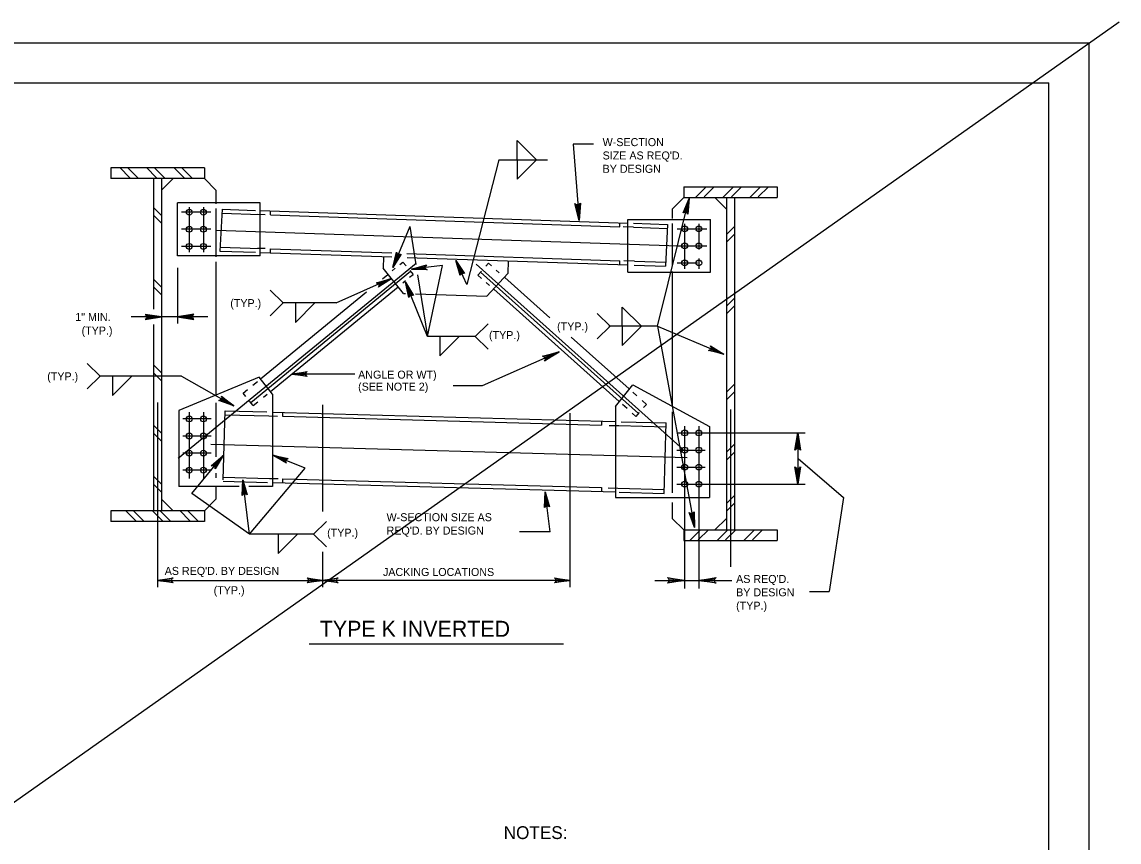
# Model space of a CAD drawing. Extents: x 634656 to 641360, y 298715 to 301183.
# Drawn here: x 635948.6 to 636359.8, y 300207.5 to 300514.8 of the extents above; entities that cross this region are included whole.
import ezdxf

# ---------------------------------------------------------------- set-up
doc = ezdxf.new("R2010")
doc.units = 0
for name, color, linetype in [('1', 7, 'Continuous'), ('2', 7, 'Continuous'), ('PLT-BNDY', 7, 'Continuous')]:
    doc.layers.add(name, color=color, linetype=linetype)

msp = doc.modelspace()

# ---------------------------------------------------------------- linework, layer by layer
at = {"layer": '1'}
for p, q in [((635497.46, 299906.13), (636359.79, 300514.83)), ((636155.15, 300469.04), (636157.39, 300440.45)), ((636127.37, 300463.21), (636115.39, 300416.47)), ((636016.96, 300460.16), (635981.91, 300460.16)), ((635981.91, 300460.16), (635981.91, 300456.16)), ((635989.04, 300456.44), (635985.23, 300460.25)), ((635992.24, 300456.16), (635988.24, 300460.16)), ((635999.07, 300456.44), (635995.26, 300460.25)), ((636002.27, 300456.16), (635998.27, 300460.16)), ((636009.34, 300456.44), (636005.53, 300460.25)), ((636012.54, 300456.16), (636008.55, 300460.16)), ((636016.96, 300460.16), (636016.96, 300456.16)), ((636016.96, 300456.16), (635981.91, 300456.16)), ((635997.94, 300456.16), (635997.94, 300407.18)), ((636000.94, 300456.16), (636000.94, 300331.63)), ((636000.94, 300451.83), (636005.26, 300456.16)), ((636021.29, 300451.83), (636016.96, 300456.16)), ((636021.29, 300451.83), (636021.29, 300446.7)), ((636196.62, 300453.01), (636231.68, 300453.01)), ((636196.62, 300453.01), (636196.62, 300449.01)), ((636201.04, 300449.01), (636205.04, 300453.01)), ((636204.25, 300449.29), (636208.06, 300453.1)), ((636211.31, 300449.01), (636215.31, 300453.01)), ((636214.52, 300449.29), (636218.33, 300453.1)), ((636221.35, 300449.01), (636225.35, 300453.01)), ((636224.55, 300449.29), (636228.36, 300453.1)), ((636231.68, 300453.01), (636231.68, 300449.01)), ((636006.95, 300427.25), (636006.95, 300447.01)), ((636037.89, 300447.01), (636006.95, 300447.01)), ((636011.3, 300445.42), (636011.3, 300428.55)), ((636016.61, 300445.42), (636016.61, 300428.55)), ((636037.89, 300427.25), (636037.89, 300447.01)), ((636186.85, 300400.8), (636198.66, 300448.68)), ((636192.3, 300444.68), (636196.62, 300449.01)), ((636196.62, 300449.01), (636231.68, 300449.01)), ((636212.65, 300444.68), (636208.32, 300449.01)), ((636212.65, 300449.01), (636212.65, 300324.48)), ((636215.65, 300449.01), (636215.65, 300324.48)), ((636000.94, 300442.34), (635997.94, 300445.34)), ((636000.94, 300439.42), (635997.94, 300442.42)), ((636019.43, 300443.52), (636008.34, 300443.52)), ((636021.29, 300444.9), (636021.29, 300426.84)), ((636023.6, 300444.65), (636022.81, 300428.97)), ((636023.55, 300443.15), (636037.89, 300442.67)), ((636023.6, 300444.65), (636036.17, 300444.23)), ((636039.77, 300442.6), (636037.06, 300442.69)), ((636037.89, 300444.17), (636175.7, 300439.49)), ((636041.79, 300442.61), (636041.79, 300444.11)), ((636041.79, 300442.53), (636172.7, 300438.09)), ((636192.3, 300444.68), (636192.3, 300441.14)), ((636093.99, 300438.14), (636087.63, 300422.85)), ((636093.99, 300438.14), (636096.28, 300423.9)), ((636172.7, 300438.09), (636172.7, 300439.54)), ((636177.81, 300437.92), (636173.97, 300438.05)), ((636175.7, 300421.04), (636175.7, 300440.81)), ((636175.7, 300440.81), (636206.63, 300440.81)), ((636177.81, 300437.92), (636190.56, 300437.49)), ((636177.86, 300439.42), (636190.61, 300438.98)), ((636190.61, 300438.98), (636189.82, 300423.3)), ((636192.3, 300439.34), (636192.3, 300423.46)), ((636194.16, 300437.32), (636205.25, 300437.32)), ((636196.98, 300439.22), (636196.98, 300422.35)), ((636202.29, 300439.22), (636202.29, 300429.6)), ((636206.63, 300421.04), (636206.63, 300440.81)), ((636212.65, 300435.19), (636215.65, 300438.2)), ((636019.43, 300437.13), (636008.34, 300437.13)), ((636021.33, 300436.87), (636194.77, 300430.99)), ((636212.65, 300432.27), (636215.65, 300435.27)), ((636019.43, 300430.74), (636008.34, 300430.74)), ((636022.81, 300428.97), (636036.18, 300428.51)), ((636022.86, 300430.47), (636037.89, 300429.96)), ((636039.79, 300429.89), (636036.91, 300429.99)), ((636041.79, 300428.39), (636041.79, 300429.82)), ((636041.79, 300429.82), (636087.18, 300428.28)), ((636194.16, 300430.93), (636205.25, 300430.93)), ((636037.89, 300427.25), (636006.95, 300427.25)), ((636021.29, 300424.93), (636021.29, 300375.04)), ((636037.89, 300428.46), (636087.19, 300426.78)), ((636084.16, 300426.88), (636084.02, 300422.57)), ((636090.24, 300423.94), (636091.38, 300424.88)), ((636091.38, 300424.88), (636092.58, 300423.42)), ((636092.81, 300428.09), (636172.7, 300425.38)), ((636093.02, 300426.58), (636175.7, 300423.78)), ((636115.39, 300416.47), (636111.23, 300425.46)), ((636130.84, 300425.3), (636130.68, 300420.6)), ((636172.7, 300423.83), (636172.7, 300425.38)), ((636178.12, 300425.2), (636174.17, 300425.33)), ((636178.12, 300425.2), (636189.87, 300424.8)), ((636202.29, 300426.22), (636202.29, 300422.35)), ((636006.95, 300422.71), (636006.95, 300401.87)), ((636007.09, 300351.43), (636096.38, 300424.49)), ((636034.34, 300372.21), (636094.24, 300421.4)), ((636091.58, 300413.09), (636084.02, 300422.57)), ((636087.31, 300421.53), (636088.54, 300422.54)), ((636093.98, 300421.72), (636095.19, 300420.24)), ((636106.2, 300423.56), (636094.58, 300422.14)), ((636100.62, 300396.97), (636106.2, 300423.56)), ((636196.47, 300354.59), (636118.84, 300424.04)), ((636120.83, 300421.43), (636119.51, 300419.95)), ((636179.66, 300368.15), (636120.51, 300421.07)), ((636123.51, 300424.42), (636122.48, 300423.27)), ((636124.61, 300423.43), (636123.51, 300424.42)), ((636127.48, 300420.87), (636126.37, 300421.86)), ((636175.7, 300421.04), (636206.63, 300421.04)), ((636178.07, 300423.7), (636189.82, 300423.3)), ((636192.3, 300421.37), (636192.3, 300370.88)), ((636194.16, 300424.53), (636201.8, 300424.53)), ((636000.94, 300415.51), (635997.94, 300418.51)), ((636066.32, 300409.52), (636087.13, 300418.84)), ((636083.74, 300418.6), (636085.69, 300420.2)), ((636091.33, 300417.07), (636092.4, 300417.95)), ((636100.62, 300396.97), (636092.31, 300417.32)), ((636093.9, 300419.18), (636095.19, 300420.24)), ((636096.89, 300420.1), (636100.62, 300396.97)), ((636120.86, 300418.74), (636119.51, 300419.95)), ((636123.87, 300416.05), (636122.58, 300417.21)), ((636122.84, 300412.03), (636130.68, 300420.6)), ((636146.44, 300403.91), (636129.52, 300419.04)), ((636000.94, 300412.59), (635997.94, 300415.59)), ((636038.04, 300381.07), (636077.75, 300413.68)), ((636041.79, 300376.39), (636089.56, 300415.62)), ((636091.58, 300413.09), (636092.31, 300413.07)), ((636096.13, 300412.94), (636122.84, 300412.03)), ((636172.44, 300372.6), (636125.44, 300414.64)), ((636212.65, 300408.36), (636215.65, 300411.36)), ((636212.65, 300405.44), (636215.65, 300408.44)), ((635997.94, 300401.46), (635997.94, 300331.63)), ((636186.85, 300400.8), (636200.62, 300325.4)), ((636186.85, 300400.8), (636211.67, 300390.37)), ((636176.16, 300377.32), (636154.49, 300396.71)), ((636149.94, 300391.23), (636121.12, 300378.46)), ((636000.94, 300383.3), (635997.94, 300386.3)), ((636000.94, 300380.38), (635997.94, 300383.38)), ((636037.45, 300381.76), (636007.35, 300369.25)), ((636008.38, 300382.08), (636027.95, 300370.94)), ((636035.13, 300378.68), (636036.93, 300380.15)), ((636042.54, 300375.38), (636037.45, 300381.76)), ((636031.48, 300375.68), (636033.15, 300377.06)), ((636032.47, 300374.48), (636031.48, 300375.68)), ((636171.04, 300370.72), (636177.57, 300378.9)), ((636179.1, 300374.7), (636177.52, 300376.1)), ((636177.57, 300378.9), (636206.24, 300363.29)), ((636212.65, 300376.15), (636215.65, 300379.15)), ((636212.65, 300373.23), (636215.65, 300376.23)), ((635999.44, 300372.21), (635999.44, 300313.77)), ((636021.29, 300372.07), (636021.29, 300351.86)), ((636035.29, 300371.05), (636033.89, 300372.75)), ((636035.29, 300371.05), (636037.06, 300372.5)), ((636039.16, 300374.22), (636040.47, 300375.3)), ((636042.54, 300375.38), (636042.54, 300340.77)), ((636061.26, 300371.41), (636061.26, 300331.36)), ((636175.41, 300369.94), (636173.65, 300371.52)), ((636182.66, 300371.5), (636181, 300372.99)), ((636182.66, 300371.5), (636181.59, 300370.3)), ((636007.35, 300369.25), (636007.35, 300340.77)), ((636011.3, 300368.62), (636011.3, 300343.72)), ((636016.61, 300368.62), (636016.61, 300343.72)), ((636024.04, 300343.26), (636024.76, 300369.15)), ((636024.72, 300367.66), (636041.15, 300367.2)), ((636024.76, 300369.15), (636040.35, 300368.72)), ((636042.43, 300368.66), (636170.96, 300365.1)), ((636046.3, 300368.62), (636046.3, 300367.06)), ((636153.97, 300368.29), (636153.97, 300302.99)), ((636171.04, 300370.72), (636171.04, 300336.65)), ((636178.66, 300367.03), (636177.32, 300368.24)), ((636179.97, 300368.49), (636178.66, 300367.03)), ((636192.3, 300368.74), (636192.3, 300338.39)), ((636214.15, 300369.66), (636214.15, 300310.65)), ((636000.94, 300360.72), (635997.94, 300363.72)), ((636019.54, 300366.07), (636008.95, 300366.07)), ((636041.15, 300367.2), (636044.39, 300367.11)), ((636046.3, 300367.06), (636165.84, 300363.74)), ((636165.84, 300365.15), (636165.84, 300363.74)), ((636168.71, 300363.66), (636172.29, 300363.56)), ((636172.29, 300363.56), (636190.01, 300363.07)), ((636173.21, 300365.03), (636190.05, 300364.57)), ((636189.32, 300338.19), (636190.05, 300364.57)), ((636196.98, 300363.37), (636196.98, 300302.6)), ((636202.29, 300363.37), (636202.29, 300302.6)), ((636206.24, 300363.29), (636206.24, 300336.65)), ((636000.94, 300357.79), (635997.94, 300360.8)), ((636019.54, 300359.68), (636008.95, 300359.68)), ((636194.04, 300360.82), (636242.12, 300360.82)), ((636239.34, 300360.82), (636239.34, 300341.64)), ((636019.33, 300356.59), (636197.89, 300351.64)), ((636212.65, 300353.57), (636215.65, 300356.57)), ((636019.54, 300353.29), (636008.95, 300353.29)), ((636012.21, 300338.1), (636023.98, 300352.43)), ((636054.72, 300347.65), (636042.68, 300352.52)), ((636194.04, 300354.43), (636204.63, 300354.43)), ((636212.65, 300350.65), (636215.65, 300353.65)), ((636239.52, 300351.23), (636256.55, 300336.59)), ((636019.54, 300346.89), (636008.95, 300346.89)), ((636033.94, 300322.93), (636054.72, 300347.65)), ((636194.04, 300348.04), (636204.63, 300348.04)), ((636000.94, 300341.59), (635997.94, 300344.59)), ((636021.29, 300345.76), (636021.29, 300344.06)), ((636024.03, 300342.78), (636040.68, 300342.32)), ((636024.07, 300344.28), (636041.36, 300343.8)), ((636033.94, 300322.93), (636031.35, 300343.28)), ((636041.36, 300343.8), (636044.58, 300343.71)), ((636046.3, 300343.66), (636165.84, 300340.34)), ((636046.3, 300343.66), (636046.3, 300342.23)), ((636000.94, 300338.67), (635997.94, 300341.67)), ((636030.07, 300340.77), (636007.35, 300340.77)), ((636021.29, 300340.77), (636021.29, 300335.96)), ((636042.54, 300340.77), (636033.62, 300340.77)), ((636042.6, 300342.26), (636171.12, 300338.7)), ((636146.54, 300323.76), (636144.64, 300338.75)), ((636165.84, 300340.34), (636165.84, 300338.76)), ((636168.31, 300340.28), (636171.89, 300340.18)), ((636171.89, 300340.18), (636189.36, 300339.69)), ((636172.48, 300338.66), (636189.32, 300338.19)), ((636194.04, 300341.64), (636242.12, 300341.64)), ((636000.94, 300335.96), (636005.26, 300331.63)), ((636033.94, 300322.93), (636012.21, 300338.1)), ((636016.96, 300331.63), (636021.29, 300335.96)), ((636171.04, 300336.65), (636206.24, 300336.65)), ((636192.3, 300334.76), (636192.3, 300328.81)), ((636212.65, 300334.44), (636215.65, 300337.44)), ((636212.65, 300331.52), (636215.65, 300334.52)), ((636256.55, 300336.59), (636251.14, 300301.37)), ((636016.96, 300331.63), (635981.91, 300331.63)), ((635981.91, 300331.63), (635981.91, 300327.63)), ((635991.22, 300327.91), (635987.41, 300331.72)), ((635994.42, 300327.63), (635990.42, 300331.63)), ((636001.25, 300327.91), (635997.44, 300331.72)), ((636004.45, 300327.63), (636000.46, 300331.63)), ((636011.52, 300327.91), (636007.71, 300331.72)), ((636014.73, 300327.63), (636010.73, 300331.63)), ((636016.96, 300331.63), (636016.96, 300327.63)), ((636016.96, 300327.63), (635981.91, 300327.63)), ((636196.62, 300324.48), (636192.3, 300328.81)), ((636212.65, 300328.81), (636208.32, 300324.48)), ((636196.62, 300324.48), (636231.68, 300324.48)), ((636196.62, 300324.48), (636196.62, 300320.48)), ((636198.86, 300320.48), (636202.86, 300324.48)), ((636202.06, 300320.76), (636205.87, 300324.58)), ((636209.13, 300320.48), (636213.13, 300324.48)), ((636212.33, 300320.76), (636216.14, 300324.58)), ((636219.17, 300320.48), (636223.16, 300324.48)), ((636222.37, 300320.76), (636226.18, 300324.58)), ((636231.68, 300324.48), (636231.68, 300320.48)), ((636196.62, 300320.48), (636231.68, 300320.48)), ((636061.26, 300316.33), (636061.26, 300302.99)), ((635999.44, 300313.77), (635999.44, 300302.99)), ((636153.97, 300313.77), (636153.97, 300302.99)), ((636185.81, 300305.58), (636196.98, 300305.58)), ((636196.98, 300305.58), (636202.29, 300305.58)), ((636202.29, 300305.58), (636214.67, 300305.58)), ((636243.73, 300301.37), (636251.14, 300301.37))]:
    msp.add_line(p, q, dxfattribs=at)
for points in [[(636157.68, 300446.62), (636157.25, 300446.36), (636157.39, 300440.45), (636157.68, 300446.62), (636157.92, 300446.95), (636157.39, 300440.45), (636156.64, 300446.3), (636156.18, 300446.48), (636157.39, 300440.45), (636155.86, 300446.79), (636156.18, 300446.48)], [(636196.66, 300443.47), (636197.1, 300443.58), (636198.66, 300448.68), (636196.66, 300443.47), (636196.36, 300443.26), (636198.66, 300448.68), (636197.64, 300443.45), (636197.98, 300443.16), (636198.66, 300448.68), (636198.16, 300442.81), (636197.98, 300443.16)], [(636090.4, 300427.69), (636089.95, 300427.66), (636087.63, 300422.85), (636090.4, 300427.69), (636090.73, 300427.86), (636087.63, 300422.85), (636089.43, 300427.87), (636089.14, 300428.2), (636087.63, 300422.85), (636089.01, 300428.58), (636089.14, 300428.2)], [(636112.92, 300420.14), (636113.2, 300420.5), (636111.23, 300425.46), (636112.92, 300420.14), (636112.82, 300419.78), (636111.23, 300425.46), (636113.71, 300420.73), (636114.15, 300420.72), (636111.23, 300425.46), (636114.51, 300420.56), (636114.15, 300420.72)], [(636100.16, 300422.12), (636099.9, 300422.49), (636094.58, 300422.14), (636100.16, 300422.12), (636100.47, 300421.92), (636094.58, 300422.14), (636099.83, 300423.05), (636099.98, 300423.46), (636094.58, 300422.14), (636100.24, 300423.76), (636099.98, 300423.46)], [(636081.79, 300416.98), (636082.14, 300416.7), (636087.11, 300418.65), (636081.79, 300416.98), (636081.43, 300417.08), (636087.11, 300418.65), (636082.38, 300416.2), (636082.36, 300415.75), (636087.11, 300418.65), (636082.2, 300415.39), (636082.36, 300415.75)], [(636093.76, 300411.93), (636094.05, 300412.27), (636092.31, 300417.32), (636093.76, 300411.93), (636093.64, 300411.58), (636092.31, 300417.32), (636094.57, 300412.49), (636095.01, 300412.46), (636092.31, 300417.32), (636095.37, 300412.28), (636095.01, 300412.46)], [(635995.14, 300403.57), (635995.35, 300403.99), (636000.94, 300404.3), (635995.14, 300403.57), (635994.84, 300403.32), (636000.94, 300404.3), (635995.36, 300404.58), (635995.15, 300404.99), (636000.94, 300404.3), (635994.84, 300405.27), (635995.15, 300404.99)], [(636012.75, 300405.03), (636012.54, 300404.61), (636006.95, 300404.3), (636012.75, 300405.03), (636013.05, 300405.28), (636006.95, 300404.3), (636012.53, 300404.02), (636012.74, 300403.61), (636006.95, 300404.3), (636013.05, 300403.33), (636012.74, 300403.61)], [(636206.84, 300393.15), (636206.87, 300392.7), (636211.67, 300390.37), (636206.84, 300393.15), (636206.67, 300393.49), (636211.67, 300390.37), (636206.66, 300392.19), (636206.33, 300391.9), (636211.67, 300390.37), (636205.95, 300391.77), (636206.33, 300391.9)], [(636144.02, 300389.45), (636144.41, 300389.14), (636149.94, 300391.23), (636144.02, 300389.45), (636143.62, 300389.57), (636149.94, 300391.23), (636144.66, 300388.58), (636144.64, 300388.09), (636149.94, 300391.23), (636144.46, 300387.68), (636144.64, 300388.09)], [(636055.23, 300382.25), (636055.02, 300382.65), (636049.69, 300382.87), (636055.23, 300382.25), (636055.52, 300382.01), (636049.69, 300382.87), (636055.01, 300383.2), (636055.2, 300383.6), (636049.69, 300382.87), (636055.49, 300383.87), (636055.2, 300383.6)], [(636023.48, 300374.28), (636023.46, 300373.83), (636027.95, 300370.94), (636023.48, 300374.28), (636023.36, 300374.63), (636027.95, 300370.94), (636023.19, 300373.34), (636022.82, 300373.09), (636027.95, 300370.94), (636022.43, 300373.01), (636022.82, 300373.09)], [(636238.57, 300354.69), (636239.01, 300354.92), (636239.34, 300360.82), (636238.57, 300354.69), (636238.3, 300354.38), (636239.34, 300360.82), (636239.63, 300354.92), (636240.07, 300354.71), (636239.34, 300360.82), (636240.36, 300354.38), (636240.07, 300354.71)], [(636019.93, 300348.59), (636020.37, 300348.49), (636023.98, 300352.43), (636019.93, 300348.59), (636019.56, 300348.52), (636023.98, 300352.43), (636020.8, 300348.14), (636020.99, 300347.74), (636023.98, 300352.43), (636021, 300347.34), (636020.99, 300347.74)], [(636047.55, 300349.8), (636047.51, 300350.25), (636042.68, 300352.52), (636047.55, 300349.8), (636047.72, 300349.47), (636042.68, 300352.52), (636047.72, 300350.77), (636048.05, 300351.06), (636042.68, 300352.52), (636048.42, 300351.2), (636048.05, 300351.06)], [(636240.11, 300347.77), (636239.67, 300347.55), (636239.34, 300341.64), (636240.11, 300347.77), (636240.38, 300348.09), (636239.34, 300341.64), (636239.05, 300347.54), (636238.61, 300347.76), (636239.34, 300341.64), (636238.32, 300348.09), (636238.61, 300347.76)], [(636031.36, 300337.7), (636031.73, 300337.95), (636031.35, 300343.28), (636031.36, 300337.7), (636031.15, 300337.39), (636031.35, 300343.28), (636032.28, 300338.03), (636032.7, 300337.88), (636031.35, 300343.28), (636033, 300337.62), (636032.7, 300337.88)], [(636144.64, 300333.17), (636145.02, 300333.43), (636144.64, 300338.75), (636144.64, 300333.17), (636144.44, 300332.86), (636144.64, 300338.75), (636145.57, 300333.5), (636145.99, 300333.36), (636144.64, 300338.75), (636146.29, 300333.1), (636145.99, 300333.36)], [(636200.3, 300330.98), (636199.95, 300330.7), (636200.62, 300325.4), (636200.3, 300330.98), (636200.49, 300331.3), (636200.62, 300325.4), (636199.4, 300330.6), (636198.98, 300330.72), (636200.62, 300325.4), (636198.66, 300330.96), (636198.98, 300330.72)], [(636004.97, 300304.88), (636004.77, 300305.28), (635999.44, 300305.58), (636004.97, 300304.88), (636005.26, 300304.64), (635999.44, 300305.58), (636004.76, 300305.84), (636004.96, 300306.24), (635999.44, 300305.58), (636005.26, 300306.5), (636004.96, 300306.24)], [(636055.72, 300306.27), (636055.93, 300305.87), (636061.26, 300305.58), (636055.72, 300306.27), (636055.44, 300306.52), (636061.26, 300305.58), (636055.93, 300305.31), (636055.74, 300304.92), (636061.26, 300305.58), (636055.44, 300304.65), (636055.74, 300304.92)], [(636066.79, 300304.88), (636066.59, 300305.28), (636061.26, 300305.58), (636066.79, 300304.88), (636067.08, 300304.64), (636061.26, 300305.58), (636066.58, 300305.84), (636066.78, 300306.24), (636061.26, 300305.58), (636067.08, 300306.5), (636066.78, 300306.24)], [(636148.43, 300306.27), (636148.64, 300305.87), (636153.97, 300305.58), (636148.43, 300306.27), (636148.15, 300306.52), (636153.97, 300305.58), (636148.64, 300305.31), (636148.45, 300304.92), (636153.97, 300305.58), (636148.15, 300304.65), (636148.45, 300304.92)], [(636190.85, 300306.35), (636191.08, 300305.9), (636196.98, 300305.58), (636190.85, 300306.35), (636190.53, 300306.62), (636196.98, 300305.58), (636191.08, 300305.29), (636190.87, 300304.85), (636196.98, 300305.58), (636190.53, 300304.55), (636190.87, 300304.85)], [(636208.42, 300304.81), (636208.19, 300305.25), (636202.29, 300305.58), (636208.42, 300304.81), (636208.73, 300304.54), (636202.29, 300305.58), (636208.18, 300305.87), (636208.4, 300306.31), (636202.29, 300305.58), (636208.73, 300306.6), (636208.4, 300306.31)]]:
    msp.add_lwpolyline(points, dxfattribs=at)
for centre in [(636011.3, 300443.52), (636016.61, 300443.52), (636011.3, 300437.13), (636016.61, 300437.13), (636196.98, 300437.32), (636202.29, 300437.32), (636011.3, 300430.74), (636016.61, 300430.74), (636196.98, 300430.93), (636202.29, 300430.93), (636196.98, 300424.53), (636202.29, 300424.53), (636011.3, 300366.07), (636016.61, 300366.07), (636011.3, 300359.68), (636016.61, 300359.68), (636196.98, 300360.82), (636202.29, 300360.82), (636196.98, 300354.43), (636202.29, 300354.43), (636011.3, 300353.29), (636016.61, 300353.29), (636011.3, 300346.89), (636016.61, 300346.89), (636196.98, 300348.04), (636202.29, 300348.04), (636196.98, 300341.64), (636202.29, 300341.64)]:
    msp.add_circle(centre, 1.09, dxfattribs=at)
at = {"layer": '2'}
for p, q in [((635547.42, 300491.99), (636333.42, 300491.99)), ((636333.42, 299927.99), (636333.42, 300491.99)), ((636134.18, 300463.21), (636134.18, 300470.46)), ((636134.18, 300470.46), (636141.43, 300463.21)), ((636162.79, 300469.04), (636155.15, 300469.04)), ((636127.37, 300463.21), (636145.6, 300463.21)), ((636134.18, 300463.21), (636134.18, 300455.96)), ((636134.18, 300455.96), (636141.43, 300463.21)), ((636066.32, 300409.52), (636046.11, 300409.52)), ((636051.1, 300409.52), (636051.1, 300402.27)), ((636051.1, 300402.27), (636058.35, 300409.52)), ((636000.94, 300404.3), (635989.48, 300404.3)), ((636006.95, 300404.3), (636000.94, 300404.3)), ((636018.31, 300404.3), (636006.95, 300404.3)), ((636186.85, 300400.8), (636168.61, 300400.8)), ((636173.6, 300400.8), (636173.6, 300393.55)), ((636173.6, 300393.55), (636180.85, 300400.8)), ((636118.52, 300396.97), (636100.62, 300396.97)), ((636105.27, 300396.97), (636105.27, 300389.72)), ((636105.27, 300389.72), (636112.52, 300396.97)), ((636008.38, 300382.08), (635977.52, 300382.08)), ((635982.51, 300382.08), (635982.51, 300374.83)), ((635982.51, 300374.83), (635989.76, 300382.08)), ((636073.38, 300382.87), (636049.69, 300382.87)), ((636121.12, 300378.46), (636110.21, 300378.46)), ((636057.84, 300322.93), (636033.94, 300322.93)), ((636044.6, 300322.93), (636044.6, 300315.68)), ((636044.6, 300315.68), (636051.85, 300322.93)), ((636146.54, 300323.76), (636135.1, 300323.76)), ((635999.44, 300305.58), (636061.26, 300305.58)), ((636153.97, 300305.58), (636061.26, 300305.58)), ((636151.56, 300281.65), (636056.3, 300281.65))]:
    msp.add_line(p, q, dxfattribs=at)
for points in [[(636041.64, 300414.27), (636046.51, 300409.52), (636041.64, 300404.77)], [(636164.14, 300405.55), (636169.02, 300400.8), (636164.14, 300396.05)], [(636173.6, 300400.8), (636173.6, 300407.93), (636180.85, 300400.8), (636173.6, 300400.8)], [(636123.39, 300401.72), (636118.52, 300396.97), (636123.39, 300392.22)], [(635973.04, 300386.83), (635977.92, 300382.08), (635973.04, 300377.33)], [(636062.72, 300327.68), (636057.84, 300322.93), (636062.72, 300318.18)]]:
    msp.add_lwpolyline(points, dxfattribs=at)
at = {"layer": 'PLT-BNDY'}
msp.add_lwpolyline([(635507.42, 300506.99), (636348.42, 300506.99), (636348.42, 299912.99), (635507.42, 299912.99)], close=True, dxfattribs=at)

# ---------------------------------------------------------------- texts
at = {"layer": '1'}
for s, height, p in [('1" MIN.', 3, (635968.59, 300402.77)), ('ANGLE OR WT)', 2.9999, (636074.59, 300381.18)), ('(SEE NOTE 2)', 2.9999, (636074.59, 300376.68)), ("AS REQ'D. BY DESIGN", 2.9999, (636002.1, 300307.63)), ('JACKING LOCATIONS', 2.9999, (636083.9, 300307.23)), ("AS REQ'D.", 3, (636216.27, 300304.61)), ('BY DESIGN', 3, (636216.27, 300299.61)), ('(TYP.)', 3, (636216.27, 300294.61))]:
    msp.add_text(s, height=height, dxfattribs=at).set_placement(p)
at = {"layer": '2'}
for s, height, p in [('W-SECTION', 3, (636166.23, 300468.3)), ("SIZE AS REQ'D.", 2.9999, (636166.23, 300463.3)), ('BY DESIGN', 3, (636166.23, 300458.3)), ('(TYP.)', 3, (636026.67, 300407.97)), ('(TYP.)', 3, (635970.95, 300397.68)), ('(TYP.)', 3, (636149.17, 300399.26)), ('(TYP.)', 3, (636123.65, 300396)), ('(TYP.)', 3, (635958.07, 300380.54)), ('W-SECTION SIZE AS', 2.9999, (636085.26, 300327.75)), ('(TYP.)', 3, (636062.98, 300321.95)), ("REQ'D. BY DESIGN", 2.9999, (636085.26, 300322.75)), ('(TYP.)', 3, (636020.45, 300300.39)), ('TYPE K INVERTED', 6, (636060.21, 300284.44)), ('NOTES:', 4.8, (636129.15, 300208.66))]:
    msp.add_text(s, height=height, dxfattribs=at).set_placement(p)

doc.saveas('drawing.dxf')
